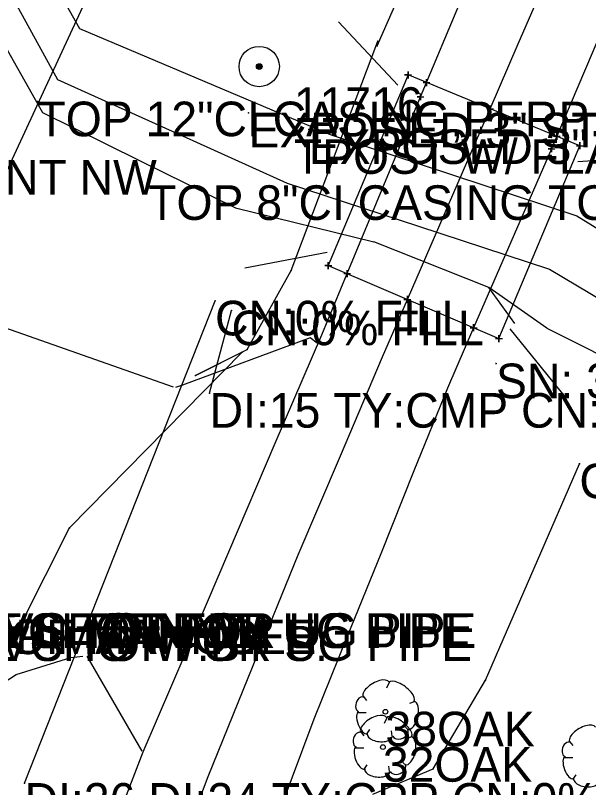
# Model space of a CAD drawing. Extents: x 997398 to 1003416, y 334596 to 337085.
# Drawn here: x 999286.4 to 999369.2, y 335737.9 to 335849.4 of the extents above; entities that cross this region are included whole.
import ezdxf

# ---------------------------------------------------------------- set-up
doc = ezdxf.new("R2010")
doc.units = 0
for name, color, linetype in [('S_BRIDGE', 7, 'Continuous'), ('S_CURB', 7, 'Continuous'), ('S_DRG_PT_SYM', 7, 'Continuous'), ('S_EDGE_CONCRETE', 7, 'Continuous'), ('S_EDGE_PAVEMENT', 7, 'Continuous'), ('S_FIBER_OPTIC_CABLE', 7, 'Continuous'), ('S_FIBER_OPTIC_CABLE_ANNOT', 7, 'Continuous'), ('S_IRON_PIN', 7, 'Continuous'), ('S_IRON_PIN_ANNOT', 7, 'Continuous'), ('S_MANHOLE_ANNOT', 7, 'Continuous'), ('S_MISC_TOPO_POINT', 7, 'Continuous'), ('S_MSC_PT_SYM', 7, 'Continuous'), ('S_PAVEMENT_CROWN', 7, 'Continuous'), ('S_SANITARY_SEWER', 7, 'Continuous'), ('S_SANITARY_SEWER_ANNOT', 7, 'Continuous'), ('S_SIDE_DRAIN', 7, 'Continuous'), ('S_SIDE_DRAIN_ANNOT', 7, 'Continuous'), ('S_STR_PT_SYM', 7, 'Continuous'), ('S_STREAM', 7, 'Continuous'), ('S_SURVEY_TEXT_ANNOT', 7, 'Continuous'), ('S_TREE', 7, 'Continuous'), ('S_TREE_ANNOT', 7, 'Continuous'), ('S_UTL_PT_SYM', 7, 'Continuous'), ('S_WALL', 7, 'Continuous')]:
    doc.layers.add(name, color=color, linetype=linetype)

msp = doc.modelspace()

# ---------------------------------------------------------------- linework, layer by layer
at = {"layer": 'S_BRIDGE'}
for p, q in [((999343.12, 335840.8), (999331.61, 335813.27)), ((999367.94, 335830.57), (999343.12, 335840.8)), ((999356.25, 335802.72), (999367.94, 335830.57)), ((999331.61, 335813.27), (999356.25, 335802.72))]:
    msp.add_line(p, q, dxfattribs=at)
for points in [[(999334.33, 335812.1), (999344.92, 335837.64), (999345.79, 335839.7)], [(999343.03, 335808.38), (999353.65, 335832.81), (999354.98, 335835.91)], [(999364.6, 335831.95), (999363.83, 335830.13), (999352.59, 335804.28)]]:
    msp.add_lwpolyline(points, dxfattribs=at)
at = {"layer": 'S_CURB'}
for points in [[(999309.27, 335795.7), (999307.46, 335796.33), (999284.06, 335804.54), (999270.5, 335812.71), (999253.53, 335827.61), (999240.32, 335848.52)], [(999266.19, 335714.69), (999272.09, 335731.57), (999275.58, 335742.68), (999279.48, 335749.62), (999286.56, 335754.18), (999294.45, 335756.63), (999296.19, 335756.83)]]:
    msp.add_lwpolyline(points, dxfattribs=at)
at = {"layer": 'S_DRG_PT_SYM'}
for points in [[(999315.26, 335808.18), (999315.26, 335808.23), (999315.26, 335808.18), (999315.21, 335808.18), (999315.26, 335808.18), (999315.26, 335808.13), (999315.26, 335808.18), (999315.31, 335808.18)], [(999317.64, 335806.76), (999317.64, 335806.81), (999317.64, 335806.76), (999317.59, 335806.76), (999317.64, 335806.76), (999317.64, 335806.71), (999317.64, 335806.76), (999317.69, 335806.76)], [(999314.48, 335794.85), (999314.48, 335794.9), (999314.48, 335794.85), (999314.43, 335794.85), (999314.48, 335794.85), (999314.48, 335794.8), (999314.48, 335794.85), (999314.53, 335794.85)], [(999287.77, 335738.51), (999287.77, 335738.56), (999287.77, 335738.51), (999287.72, 335738.51), (999287.77, 335738.51), (999287.77, 335738.46), (999287.77, 335738.51), (999287.82, 335738.51)]]:
    msp.add_lwpolyline(points, dxfattribs=at)
at = {"layer": 'S_EDGE_CONCRETE'}
for points in [[(999329.99, 335802.05), (999329, 335802.81), (999310.58, 335796), (999309.53, 335795.64)], [(999296.74, 335756.86), (999304.71, 335743.14)]]:
    msp.add_lwpolyline(points, dxfattribs=at)
at = {"layer": 'S_EDGE_PAVEMENT'}
for points in [[(999345.79, 335839.7), (999350.09, 335849.94), (999355.27, 335862.25), (999360.45, 335874.56), (999365.63, 335886.87), (999371.17, 335900.18), (999376.72, 335913.48), (999382.27, 335926.79), (999387.81, 335940.1), (999394.44, 335955.02), (999401.06, 335969.95), (999407.69, 335984.87), (999414.31, 335999.8)], [(999431.8, 335993.95), (999426.44, 335980.73), (999421.08, 335967.51), (999415.72, 335954.3), (999410.36, 335941.08), (999404.58, 335927.18), (999398.8, 335913.28), (999393.01, 335899.39), (999387.23, 335885.49), (999381.38, 335871.65), (999375.53, 335857.81), (999369.68, 335843.97), (999364.6, 335831.95)], [(999259.87, 335596.96), (999264.04, 335615.85), (999268.21, 335634.73), (999272.57, 335649.27), (999276.93, 335663.8), (999281.3, 335678.34), (999285.66, 335692.87), (999290.47, 335705.41), (999295.28, 335717.95), (999300.08, 335730.5), (999304.89, 335743.04), (999311.07, 335757.48), (999317.24, 335771.92), (999323.96, 335787.59), (999330.67, 335803.27), (999334.33, 335812.1)], [(999352.59, 335804.28), (999348.8, 335795.55), (999343.98, 335783.6), (999339.17, 335771.64), (999334.35, 335759.69), (999329.54, 335747.73), (999324.76, 335734.99), (999319.98, 335722.25), (999315.21, 335709.51), (999310.43, 335696.77), (999306.09, 335683.91), (999301.75, 335671.05), (999297.41, 335658.19), (999293.07, 335645.33), (999289.63, 335632.59), (999286.2, 335619.85), (999282.76, 335607.12), (999279.33, 335594.38)]]:
    msp.add_lwpolyline(points, dxfattribs=at)
at = {"layer": 'S_FIBER_OPTIC_CABLE'}
for p, q in [((999338.68, 335845.02), (999342.96, 335854.77)), ((999326.23, 335812.55), (999338.76, 335845.67)), ((999319.91, 335801.15), (999326.23, 335812.55)), ((999312.45, 335797.4), (999319.91, 335801.15)), ((999294.24, 335775.36), (999319.18, 335800.77)), ((999319.18, 335800.77), (999312.45, 335797.4)), ((999354.29, 335753.38), (999367.86, 335784.65)), ((999282.47, 335752.03), (999294.24, 335775.36)), ((999346.74, 335740.59), (999354.29, 335753.38)), ((999338.02, 335736.93), (999346.74, 335740.59))]:
    msp.add_line(p, q, dxfattribs=at)
at = {"layer": 'S_IRON_PIN'}
for radius in [2.91, 0.411, 0.262, 0.212, 0.145, 0.0822, 0.0581]:
    msp.add_circle((999321.64, 335842.02), radius, dxfattribs=at)
at = {"layer": 'S_MSC_PT_SYM'}
for points in [[(999289.63, 335836.95), (999289.63, 335837), (999289.63, 335836.95), (999289.58, 335836.95), (999289.63, 335836.95), (999289.63, 335836.9), (999289.63, 335836.95), (999289.68, 335836.95)], [(999320.1, 335835.34), (999320.1, 335835.39), (999320.1, 335835.34), (999320.05, 335835.34), (999320.1, 335835.34), (999320.1, 335835.29), (999320.1, 335835.34), (999320.15, 335835.34)], [(999328.8, 335832.94), (999328.8, 335832.99), (999328.8, 335832.94), (999328.75, 335832.94), (999328.8, 335832.94), (999328.8, 335832.89), (999328.8, 335832.94), (999328.85, 335832.94)], [(999305.61, 335824.86), (999305.61, 335824.91), (999305.61, 335824.86), (999305.56, 335824.86), (999305.61, 335824.86), (999305.61, 335824.81), (999305.61, 335824.86), (999305.66, 335824.86)], [(999355.82, 335799.11), (999355.82, 335799.16), (999355.82, 335799.11), (999355.77, 335799.11), (999355.82, 335799.11), (999355.82, 335799.06), (999355.82, 335799.11), (999355.87, 335799.11)]]:
    msp.add_lwpolyline(points, dxfattribs=at)
at = {"layer": 'S_PAVEMENT_CROWN'}
for points in [[(999354.98, 335835.91), (999359.04, 335845.32), (999364.44, 335857.84), (999369.84, 335870.36), (999375.24, 335882.88), (999380.6, 335896.16), (999385.95, 335909.44), (999391.31, 335922.72), (999396.66, 335936.01), (999402.74, 335950.26), (999408.82, 335964.51), (999414.9, 335978.77), (999420.98, 335993.02)], [(999277.22, 335631.74), (999281.77, 335646.2), (999286.31, 335660.66), (999290.86, 335675.12), (999295.4, 335689.58), (999300.12, 335702.05), (999304.83, 335714.52), (999309.55, 335726.99), (999314.27, 335739.46), (999320.77, 335755.48), (999327.27, 335771.5), (999333.35, 335785.79), (999339.42, 335800.08), (999343.03, 335808.38)]]:
    msp.add_lwpolyline(points, dxfattribs=at)
at = {"layer": 'S_SANITARY_SEWER'}
msp.add_line((999357.64, 335983.75), (999255.64, 335763.04), dxfattribs=at)
at = {"layer": 'S_SIDE_DRAIN'}
for p, q in [((999287.77, 335738.51), (999315.26, 335808.18)), ((999314.48, 335794.85), (999317.64, 335806.76))]:
    msp.add_line(p, q, dxfattribs=at)
at = {"layer": 'S_STR_PT_SYM'}
for points in [[(999343.12, 335840.8), (999343.12, 335841.3), (999343.12, 335840.8), (999342.62, 335840.8), (999343.12, 335840.8), (999343.12, 335840.3), (999343.12, 335840.8), (999343.62, 335840.8)], [(999345.79, 335839.7), (999345.79, 335840.2), (999345.79, 335839.7), (999345.29, 335839.7), (999345.79, 335839.7), (999345.79, 335839.2), (999345.79, 335839.7), (999346.29, 335839.7)], [(999344.92, 335837.64), (999344.92, 335838.14), (999344.92, 335837.64), (999344.42, 335837.64), (999344.92, 335837.64), (999344.92, 335837.14), (999344.92, 335837.64), (999345.42, 335837.64)], [(999354.98, 335835.91), (999354.98, 335836.41), (999354.98, 335835.91), (999354.48, 335835.91), (999354.98, 335835.91), (999354.98, 335835.41), (999354.98, 335835.91), (999355.48, 335835.91)], [(999353.65, 335832.81), (999353.65, 335833.31), (999353.65, 335832.81), (999353.15, 335832.81), (999353.65, 335832.81), (999353.65, 335832.31), (999353.65, 335832.81), (999354.15, 335832.81)], [(999364.6, 335831.95), (999364.6, 335832.45), (999364.6, 335831.95), (999364.1, 335831.95), (999364.6, 335831.95), (999364.6, 335831.45), (999364.6, 335831.95), (999365.1, 335831.95)], [(999363.83, 335830.13), (999363.83, 335830.63), (999363.83, 335830.13), (999363.33, 335830.13), (999363.83, 335830.13), (999363.83, 335829.63), (999363.83, 335830.13), (999364.33, 335830.13)], [(999367.94, 335830.57), (999367.94, 335831.07), (999367.94, 335830.57), (999367.44, 335830.57), (999367.94, 335830.57), (999367.94, 335830.07), (999367.94, 335830.57), (999368.44, 335830.57)], [(999331.61, 335813.27), (999331.61, 335813.77), (999331.61, 335813.27), (999331.11, 335813.27), (999331.61, 335813.27), (999331.61, 335812.77), (999331.61, 335813.27), (999332.11, 335813.27)], [(999334.33, 335812.1), (999334.33, 335812.6), (999334.33, 335812.1), (999333.83, 335812.1), (999334.33, 335812.1), (999334.33, 335811.6), (999334.33, 335812.1), (999334.83, 335812.1)], [(999343.03, 335808.38), (999343.03, 335808.88), (999343.03, 335808.38), (999342.53, 335808.38), (999343.03, 335808.38), (999343.03, 335807.88), (999343.03, 335808.38), (999343.53, 335808.38)], [(999352.59, 335804.28), (999352.59, 335804.78), (999352.59, 335804.28), (999352.09, 335804.28), (999352.59, 335804.28), (999352.59, 335803.78), (999352.59, 335804.28), (999353.09, 335804.28)], [(999356.25, 335802.72), (999356.25, 335803.22), (999356.25, 335802.72), (999355.75, 335802.72), (999356.25, 335802.72), (999356.25, 335802.22), (999356.25, 335802.72), (999356.75, 335802.72)]]:
    msp.add_lwpolyline(points, dxfattribs=at)
at = {"layer": 'S_STREAM'}
for points in [[(999266.56, 335913.42), (999272.51, 335895.83), (999278.46, 335878.24), (999287.08, 335862.87), (999295.7, 335847.5)], [(999262.33, 335911.44), (999267.46, 335893.9), (999272.6, 335876.36), (999282.55, 335858.26), (999292.5, 335840.15)], [(999258.36, 335906.71), (999263.07, 335891.05), (999267.78, 335875.39), (999279.06, 335855.39), (999290.34, 335835.39)], [(999295.7, 335847.5), (999313.8, 335839.85), (999331.89, 335832.2)], [(999292.5, 335840.15), (999309.09, 335832.66), (999325.68, 335825.18)], [(999290.34, 335835.39), (999304.27, 335828.51), (999318.19, 335821.63)], [(999331.89, 335832.2), (999349.69, 335826.31), (999367.5, 335820.43), (999381.08, 335812.09), (999394.65, 335803.75), (999408.23, 335795.41), (999421.81, 335787.07), (999434.28, 335784.52), (999446.75, 335781.96), (999459.22, 335779.4), (999471.69, 335776.85), (999491.33, 335765.68), (999510.96, 335754.51)], [(999325.68, 335825.18), (999344.61, 335818.97), (999363.54, 335812.75), (999377.19, 335804.59), (999390.85, 335796.43), (999404.51, 335788.27), (999418.17, 335780.11), (999430.58, 335776.57), (999442.99, 335773.03), (999455.4, 335769.5), (999467.81, 335765.96), (999489.15, 335758.72), (999510.5, 335751.47)], [(999318.19, 335821.63), (999338.17, 335816.68)], [(999358.54, 335804.89), (999354.79, 335810.09), (999338.17, 335816.68)], [(999363.15, 335804.23), (999354.79, 335810.09)], [(999363.15, 335804.23), (999376.49, 335797.55), (999389.84, 335790.87), (999403.19, 335784.2), (999416.53, 335777.52), (999429.2, 335774.06), (999441.86, 335770.61), (999454.53, 335767.16), (999467.19, 335763.7), (999487.73, 335755.71), (999508.28, 335747.72)]]:
    msp.add_lwpolyline(points, dxfattribs=at)
at = {"layer": 'S_TREE'}
for p, q in [((999340.42, 335753.06), (999340.03, 335752.21)), ((999336.62, 335751.05), (999337.13, 335750.46)), ((999343.99, 335750.27), (999343.33, 335750)), ((999335.97, 335748.72), (999337.09, 335748.72)), ((999340.05, 335747.96), (999339.66, 335747.1)), ((999343.21, 335746.16), (999342.75, 335746.59)), ((999336.25, 335745.94), (999336.76, 335745.36)), ((999337.13, 335745.54), (999337.59, 335746.24)), ((999340.81, 335745.27), (999340.73, 335746.05)), ((999343.62, 335745.17), (999342.96, 335744.9)), ((999366.42, 335744.52), (999366.92, 335743.94)), ((999335.59, 335743.62), (999336.72, 335743.62)), ((999365.76, 335742.2), (999366.89, 335742.2)), ((999336.76, 335740.44), (999337.22, 335741.14)), ((999340.44, 335740.17), (999340.36, 335740.94)), ((999342.84, 335741.06), (999342.38, 335741.49)), ((999366.92, 335739.02), (999367.39, 335739.72))]:
    msp.add_line(p, q, dxfattribs=at)
for centre in [(999339.86, 335748.82), (999339.49, 335743.71)]:
    msp.add_circle(centre, 0.341, dxfattribs=at)
for centre, major_axis, ratio, start_param, end_param in [((999338.53, 335752.02), (1.86, 1.08), 0.471018, 0, 3.141593), ((999342.18, 335751.69), (-1.81, 1.36), 0.405113, 3.141593, 6.283186), ((999336.29, 335749.9), (0.31, 1.03), 0.646762, 0, 3.141593), ((999343.54, 335748.29), (0.46, 2.04), 0.482994, 3.141593, 6.283185), ((999336.6, 335747.25), (-0.61, 1.6), 0.420543, 6.283185, 9.424777), ((999338.16, 335746.91), (1.86, 1.08), 0.471018, 0, 3.141593), ((999341.81, 335746.59), (-1.81, 1.36), 0.405113, 3.141593, 6.283186), ((999368.32, 335745.5), (1.86, 1.08), 0.471018, 0, 3.141593), ((999335.92, 335744.8), (0.31, 1.03), 0.646762, 0, 3.141593), ((999339.06, 335745.47), (-1.83, 0.19), 0.529943, 0, 3.141593), ((999342.02, 335745.76), (1.09, 0.46), 0.711534, 3.141592, 6.283185), ((999343.17, 335743.18), (0.46, 2.04), 0.482994, 3.141593, 6.283185), ((999366.09, 335743.38), (0.31, 1.03), 0.646762, 0, 3.141593), ((999336.23, 335742.15), (-0.61, 1.6), 0.420543, 6.283185, 9.424777), ((999366.39, 335740.73), (-0.61, 1.6), 0.420543, 6.283185, 9.424777), ((999341.65, 335740.66), (1.09, 0.46), 0.711534, 3.141592, 6.283185), ((999338.69, 335740.37), (-1.83, 0.19), 0.529943, 0, 3.141593), ((999368.86, 335738.95), (-1.83, 0.19), 0.529943, 0, 3.141593)]:
    msp.add_ellipse(centre, major_axis=major_axis, ratio=ratio, start_param=start_param, end_param=end_param, dxfattribs=at)
at = {"layer": 'S_UTL_PT_SYM'}
for points in [[(999338.68, 335845.02), (999338.68, 335845.07), (999338.68, 335845.02), (999338.63, 335845.02), (999338.68, 335845.02), (999338.68, 335844.97), (999338.68, 335845.02), (999338.73, 335845.02)], [(999338.76, 335845.67), (999338.76, 335845.72), (999338.76, 335845.67), (999338.71, 335845.67), (999338.76, 335845.67), (999338.76, 335845.62), (999338.76, 335845.67), (999338.81, 335845.67)], [(999326.23, 335812.55), (999326.23, 335812.6), (999326.23, 335812.55), (999326.18, 335812.55), (999326.23, 335812.55), (999326.23, 335812.5), (999326.23, 335812.55), (999326.28, 335812.55)], [(999319.91, 335801.15), (999319.91, 335801.2), (999319.91, 335801.15), (999319.86, 335801.15), (999319.91, 335801.15), (999319.91, 335801.1), (999319.91, 335801.15), (999319.96, 335801.15)], [(999319.18, 335800.77), (999319.18, 335800.82), (999319.18, 335800.77), (999319.12, 335800.77), (999319.18, 335800.77), (999319.18, 335800.72), (999319.18, 335800.77), (999319.23, 335800.77)], [(999312.45, 335797.4), (999312.45, 335797.45), (999312.45, 335797.4), (999312.4, 335797.4), (999312.45, 335797.4), (999312.45, 335797.35), (999312.45, 335797.4), (999312.5, 335797.4)], [(999367.86, 335784.65), (999367.86, 335784.7), (999367.86, 335784.65), (999367.81, 335784.65), (999367.86, 335784.65), (999367.86, 335784.6), (999367.86, 335784.65), (999367.91, 335784.65)], [(999294.24, 335775.36), (999294.24, 335775.41), (999294.24, 335775.36), (999294.19, 335775.36), (999294.24, 335775.36), (999294.24, 335775.31), (999294.24, 335775.36), (999294.29, 335775.36)], [(999354.29, 335753.38), (999354.29, 335753.43), (999354.29, 335753.38), (999354.24, 335753.38), (999354.29, 335753.38), (999354.29, 335753.33), (999354.29, 335753.38), (999354.34, 335753.38)], [(999346.74, 335740.59), (999346.74, 335740.64), (999346.74, 335740.59), (999346.69, 335740.59), (999346.74, 335740.59), (999346.74, 335740.54), (999346.74, 335740.59), (999346.79, 335740.59)]]:
    msp.add_lwpolyline(points, dxfattribs=at)
at = {"layer": 'S_WALL'}
for points in [[(999333.08, 335848.46), (999341.64, 335839.31)], [(999367.62, 335828.3), (999377.79, 335828.97)], [(999331.46, 335815.14), (999319.55, 335812.91)], [(999357.8, 335804.13), (999365.4, 335794.72)]]:
    msp.add_lwpolyline(points, dxfattribs=at)

# ---------------------------------------------------------------- texts
at = {"layer": 'S_FIBER_OPTIC_CABLE_ANNOT'}
for s, p in [('ARROW: CONT NW', (999245.57, 335823.53)), ('CONT.N.', (999367.86, 335779.65))]:
    msp.add_text(s, height=5, dxfattribs=at).set_placement(p)
at = {"layer": 'S_IRON_PIN_ANNOT'}
for s, p in [('11716', (999326.64, 335834.02)), ('TPOST W/ FLAGGING', (999326.64, 335826.52))]:
    msp.add_text(s, height=5, dxfattribs=at).set_placement(p)
at = {"layer": 'S_MANHOLE_ANNOT'}
msp.add_text('BOTTOM OF MANHOLE', height=5, dxfattribs=at).set_placement((999255.23, 335757.14))
at = {"layer": 'S_MISC_TOPO_POINT'}
for p in [(999254.8, 335758.03), (999255.64, 335758.04), (999255.03, 335756.15)]:
    msp.add_text('SURFACE SHOT FOR UG PIPE', height=5, dxfattribs=at).set_placement(p)
at = {"layer": 'S_SANITARY_SEWER_ANNOT'}
for s, p in [('DI:4 TY:PVC TO NNW', (999254.8, 335758.03)), ('TOP CL OF MANHOLE', (999255.23, 335757.14)), ('DI:8 TY:PVC TO NNE', (999255.64, 335758.04)), ('DI:6 TY:PVC TO W.BY S.', (999255.03, 335756.15))]:
    msp.add_text(s, height=5, dxfattribs=at).set_placement(p)
at = {"layer": 'S_SIDE_DRAIN_ANNOT'}
for s, p in [('CN:0% FILL', (999315.26, 335803.18)), ('CN:0% FILL', (999317.64, 335801.76)), ('DI:15 TY:CMP CN:0% FILL', (999314.48, 335789.85)), ('DI:26 DI:24 TY:CPP CN:0% FILL', (999287.77, 335733.51))]:
    msp.add_text(s, height=5, dxfattribs=at).set_placement(p)
at = {"layer": 'S_SURVEY_TEXT_ANNOT'}
for s, p in [('TOP 12"CI CASING,PERP.. TO STR,', (999289.63, 335831.95)), ('EXPOSED 3" STEEL PIPE.. ..PERP.', (999320.1, 335830.34)), ('EXPOSED 3" PLAS, PERP.. TO STRE', (999328.8, 335827.94)), ('TOP 8"CI CASING TOP 8"CI CASING', (999305.61, 335819.86)), ('SN: 331-0, 0.15', (999355.82, 335794.11))]:
    msp.add_text(s, height=5, dxfattribs=at).set_placement(p)
at = {"layer": 'S_TREE_ANNOT'}
for s, p in [('38OAK', (999339.86, 335743.82)), ('32OAK', (999339.49, 335738.71))]:
    msp.add_text(s, height=5, dxfattribs=at).set_placement(p)

doc.saveas('drawing.dxf')
